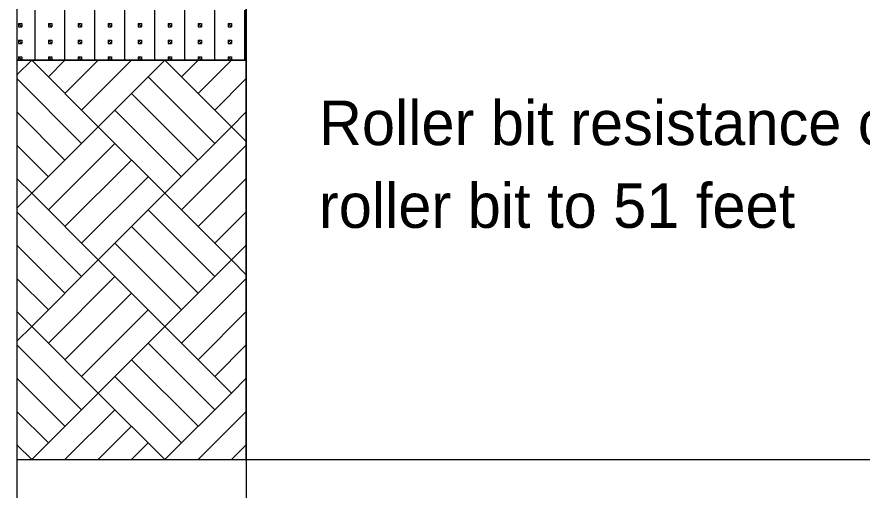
# Model space of a CAD drawing. Extents: x 9422 to 9552, y 6780 to 6860.
# Drawn here: x 9438.314 to 9442.547, y 6795.858 to 6798.227 of the extents above; entities that cross this region are included whole.
import ezdxf

# ---------------------------------------------------------------- set-up
doc = ezdxf.new("R2010")
doc.units = 0
doc.layers.add('7', color=7, linetype='Continuous')
doc.layers.add('8', color=7, linetype='Continuous')

msp = doc.modelspace()

# ---------------------------------------------------------------- linework, layer by layer
at = {"layer": '7'}
for p, q in [((9438.3144, 6822.0107), (9438.3144, 6798.0107)), ((9439.4627, 6798.0107), (9439.4627, 6822.0107)), ((9438.3144, 6798.0107), (9438.3144, 6797.0107)), ((9439.4627, 6798.0107), (9438.3144, 6798.0107)), ((9438.3144, 6798.0107), (9439.4627, 6798.0107)), ((9439.4627, 6797.0107), (9439.4627, 6798.0107)), ((9438.3144, 6797.0107), (9438.3144, 6796.0107)), ((9439.4627, 6796.0107), (9439.4627, 6797.0107)), ((9438.3144, 6796.0107), (9439.4627, 6796.0107))]:
    msp.add_line(p, q, dxfattribs=at)
for points in [[(9438.3144, 6822.0384), (9438.3144, 6796.9829)], [(9439.4627, 6822.0384), (9439.4627, 6796.9829)], [(9438.3144, 6797.0385), (9438.3144, 6792.0107)], [(9439.4627, 6797.0385), (9439.4627, 6792.0107)], [(9439.4627, 6796.0107), (9450.4053, 6796.0107)]]:
    msp.add_lwpolyline(points, dxfattribs=at)
at = {"layer": '8'}
for p, q in [((9438.4053, 6798.1774), (9438.4053, 6798.2607)), ((9438.5553, 6798.1774), (9438.5553, 6798.2607)), ((9438.7053, 6798.1774), (9438.7053, 6798.2607)), ((9438.8553, 6798.1774), (9438.8553, 6798.2607)), ((9439.0053, 6798.1774), (9439.0053, 6798.2607)), ((9439.1553, 6798.1774), (9439.1553, 6798.2607)), ((9439.3053, 6798.1774), (9439.3053, 6798.2607)), ((9439.4553, 6798.1774), (9439.4553, 6798.2607)), ((9438.4053, 6798.094), (9438.4053, 6798.1774)), ((9438.5553, 6798.094), (9438.5553, 6798.1774)), ((9438.7053, 6798.094), (9438.7053, 6798.1774)), ((9438.8553, 6798.094), (9438.8553, 6798.1774)), ((9439.0053, 6798.094), (9439.0053, 6798.1774)), ((9439.1553, 6798.094), (9439.1553, 6798.1774)), ((9439.3053, 6798.094), (9439.3053, 6798.1774)), ((9439.4553, 6798.094), (9439.4553, 6798.1774)), ((9438.4053, 6798.0107), (9438.4053, 6798.094)), ((9438.5553, 6798.0107), (9438.5553, 6798.094)), ((9438.7053, 6798.0107), (9438.7053, 6798.094)), ((9438.8553, 6798.0107), (9438.8553, 6798.094)), ((9439.0053, 6798.0107), (9439.0053, 6798.094)), ((9439.1553, 6798.0107), (9439.1553, 6798.094)), ((9439.3053, 6798.0107), (9439.3053, 6798.094)), ((9439.4553, 6798.0107), (9439.4553, 6798.094)), ((9438.3886, 6798.0107), (9438.3144, 6797.9366)), ((9438.3886, 6798.0107), (9438.7219, 6797.6774)), ((9438.3886, 6798.0107), (9438.3886, 6798.0107)), ((9438.5553, 6798.0107), (9438.4719, 6797.9274)), ((9438.7219, 6798.0107), (9438.5553, 6797.844)), ((9438.8886, 6798.0107), (9438.6386, 6797.7607)), ((9439.0553, 6798.0107), (9438.7219, 6797.6774)), ((9439.0553, 6798.0107), (9438.7219, 6797.6774)), ((9439.0553, 6798.0107), (9439.0553, 6798.0107)), ((9439.0553, 6798.0107), (9439.3886, 6797.6774)), ((9439.0553, 6798.0107), (9439.0553, 6798.0107)), ((9439.2219, 6798.0107), (9439.1386, 6797.9274)), ((9439.3886, 6798.0107), (9439.2219, 6797.844)), ((9438.3144, 6797.9182), (9438.6386, 6797.594)), ((9438.9719, 6797.9274), (9439.3053, 6797.594)), ((9439.4627, 6797.9182), (9439.3053, 6797.7607)), ((9438.8886, 6797.844), (9439.2219, 6797.5107)), ((9438.3144, 6797.7515), (9438.5553, 6797.5107)), ((9438.8053, 6797.7607), (9439.1386, 6797.4274)), ((9439.4627, 6797.7515), (9439.3886, 6797.6774)), ((9439.4627, 6797.7515), (9439.3886, 6797.6774)), ((9438.7219, 6797.6774), (9438.3886, 6797.344)), ((9438.7219, 6797.6774), (9438.3886, 6797.344)), ((9439.0553, 6797.344), (9438.7219, 6797.6774)), ((9438.7219, 6797.6774), (9439.0553, 6797.344)), ((9439.3886, 6797.6774), (9439.0553, 6797.344)), ((9439.3886, 6797.6774), (9439.0553, 6797.344)), ((9439.4627, 6797.6032), (9439.3886, 6797.6774)), ((9439.3886, 6797.6774), (9439.4627, 6797.6032)), ((9438.3144, 6797.5848), (9438.4719, 6797.4274)), ((9438.8053, 6797.594), (9438.4719, 6797.2607)), ((9439.4627, 6797.5848), (9439.1386, 6797.2607)), ((9438.8886, 6797.5107), (9438.5553, 6797.1774)), ((9438.3886, 6797.344), (9438.3144, 6797.4182)), ((9438.9719, 6797.4274), (9438.6386, 6797.094)), ((9439.4627, 6797.4182), (9439.2219, 6797.1774)), ((9438.3886, 6797.344), (9438.3144, 6797.2699)), ((9438.3886, 6797.344), (9438.7219, 6797.0107)), ((9439.0553, 6797.344), (9438.7219, 6797.0107)), ((9439.0553, 6797.344), (9439.3886, 6797.0107)), ((9438.3144, 6797.2515), (9438.6386, 6796.9274)), ((9438.9719, 6797.2607), (9439.3053, 6796.9274)), ((9439.4627, 6797.2515), (9439.3053, 6797.094)), ((9438.8886, 6797.1774), (9439.2219, 6796.844)), ((9438.3144, 6797.0848), (9438.5553, 6796.844)), ((9438.8053, 6797.094), (9439.1386, 6796.7607)), ((9439.4627, 6797.0848), (9439.3886, 6797.0107)), ((9439.4627, 6797.0848), (9439.3886, 6797.0107)), ((9438.7219, 6797.0107), (9438.3886, 6796.6774)), ((9438.7219, 6797.0107), (9438.3886, 6796.6774)), ((9438.7219, 6797.0107), (9438.7219, 6797.0107)), ((9438.7219, 6797.0107), (9438.7219, 6797.0107)), ((9438.7219, 6797.0107), (9438.7219, 6797.0107)), ((9438.7219, 6797.0107), (9438.7219, 6797.0107)), ((9438.7219, 6797.0107), (9439.0553, 6796.6774)), ((9439.3886, 6797.0107), (9439.0553, 6796.6774)), ((9439.3886, 6797.0107), (9439.3886, 6797.0107)), ((9439.3886, 6797.0107), (9439.3886, 6797.0107)), ((9439.3886, 6797.0107), (9439.3886, 6797.0107)), ((9439.3886, 6797.0107), (9439.3886, 6797.0107)), ((9439.3886, 6797.0107), (9439.4627, 6796.9365)), ((9438.3144, 6796.9182), (9438.4719, 6796.7607)), ((9438.8053, 6796.9274), (9438.4719, 6796.594)), ((9439.4627, 6796.9182), (9439.1386, 6796.594)), ((9438.8886, 6796.844), (9438.5553, 6796.5107)), ((9438.3886, 6796.6774), (9438.3145, 6796.7515)), ((9438.9719, 6796.7607), (9438.6386, 6796.4274)), ((9439.4627, 6796.7515), (9439.2219, 6796.5107)), ((9438.3886, 6796.6774), (9438.3145, 6796.6032)), ((9438.3886, 6796.6774), (9438.7219, 6796.344)), ((9439.0553, 6796.6774), (9438.7219, 6796.344)), ((9439.0553, 6796.6774), (9439.3886, 6796.344)), ((9438.9719, 6796.594), (9439.3053, 6796.2607)), ((9438.3144, 6796.5848), (9438.6386, 6796.2607)), ((9439.4627, 6796.5848), (9439.3053, 6796.4274)), ((9438.8886, 6796.5107), (9439.2219, 6796.1774)), ((9438.8053, 6796.4274), (9439.1386, 6796.094)), ((9438.3144, 6796.4182), (9438.5553, 6796.1774)), ((9439.4627, 6796.4182), (9439.3886, 6796.344)), ((9439.4627, 6796.4182), (9439.3886, 6796.344)), ((9438.7219, 6796.344), (9438.3886, 6796.0107)), ((9438.7219, 6796.344), (9438.3886, 6796.0107)), ((9438.7219, 6796.344), (9439.0553, 6796.0107)), ((9439.3886, 6796.344), (9439.0553, 6796.0107)), ((9439.3886, 6796.344), (9439.3886, 6796.344)), ((9439.3886, 6796.344), (9439.3886, 6796.344)), ((9439.3886, 6796.344), (9439.3886, 6796.344)), ((9439.3886, 6796.344), (9439.3886, 6796.344)), ((9438.8053, 6796.2607), (9438.5553, 6796.0107)), ((9438.3144, 6796.2515), (9438.4719, 6796.094)), ((9439.4627, 6796.2515), (9439.2219, 6796.0107)), ((9438.8886, 6796.1774), (9438.7219, 6796.0107)), ((9438.9719, 6796.094), (9438.8886, 6796.0107)), ((9439.4627, 6796.0849), (9439.3886, 6796.0107)), ((9438.3886, 6796.0107), (9438.3145, 6796.0848)), ((9438.7219, 6796.0107), (9438.7219, 6796.0107)), ((9438.7219, 6796.0107), (9438.7219, 6796.0107)), ((9438.7219, 6796.0107), (9438.7219, 6796.0107)), ((9438.7219, 6796.0107), (9438.7219, 6796.0107)), ((9439.3886, 6796.0107), (9439.3886, 6796.0107)), ((9439.3886, 6796.0107), (9439.3886, 6796.0107)), ((9439.3886, 6796.0107), (9439.3886, 6796.0107)), ((9439.3886, 6796.0107), (9439.3886, 6796.0107))]:
    msp.add_line(p, q, dxfattribs=at)
for points in [[(9438.3219, 6798.1774), (9438.3386, 6798.1774), (9438.3219, 6798.194)], [(9438.3386, 6798.194), (9438.3386, 6798.1774), (9438.3219, 6798.194), (9438.3386, 6798.194)], [(9438.4719, 6798.1774), (9438.4886, 6798.1774), (9438.4719, 6798.194)], [(9438.4886, 6798.194), (9438.4886, 6798.1774), (9438.4719, 6798.194), (9438.4886, 6798.194)], [(9438.6219, 6798.1774), (9438.6386, 6798.1774), (9438.6219, 6798.194)], [(9438.6386, 6798.194), (9438.6386, 6798.1774), (9438.6219, 6798.194), (9438.6386, 6798.194)], [(9438.7719, 6798.1774), (9438.7886, 6798.1774), (9438.7719, 6798.194)], [(9438.7886, 6798.194), (9438.7886, 6798.1774), (9438.7719, 6798.194), (9438.7886, 6798.194)], [(9438.9219, 6798.1774), (9438.9386, 6798.1774), (9438.9219, 6798.194)], [(9438.9386, 6798.194), (9438.9386, 6798.1774), (9438.9219, 6798.194), (9438.9386, 6798.194)], [(9439.0719, 6798.1774), (9439.0886, 6798.1774), (9439.0719, 6798.194)], [(9439.0886, 6798.194), (9439.0886, 6798.1774), (9439.0719, 6798.194), (9439.0886, 6798.194)], [(9439.2219, 6798.1774), (9439.2386, 6798.1774), (9439.2219, 6798.194)], [(9439.2386, 6798.194), (9439.2386, 6798.1774), (9439.2219, 6798.194), (9439.2386, 6798.194)], [(9439.3719, 6798.1774), (9439.3886, 6798.1774), (9439.3719, 6798.194)], [(9439.3886, 6798.194), (9439.3886, 6798.1774), (9439.3719, 6798.194), (9439.3886, 6798.194)], [(9438.3219, 6798.094), (9438.3386, 6798.094), (9438.3219, 6798.1107)], [(9438.3386, 6798.1107), (9438.3386, 6798.094), (9438.3219, 6798.1107), (9438.3386, 6798.1107)], [(9438.4719, 6798.094), (9438.4886, 6798.094), (9438.4719, 6798.1107)], [(9438.4886, 6798.1107), (9438.4886, 6798.094), (9438.4719, 6798.1107), (9438.4886, 6798.1107)], [(9438.6219, 6798.094), (9438.6386, 6798.094), (9438.6219, 6798.1107)], [(9438.6386, 6798.1107), (9438.6386, 6798.094), (9438.6219, 6798.1107), (9438.6386, 6798.1107)], [(9438.7719, 6798.094), (9438.7886, 6798.094), (9438.7719, 6798.1107)], [(9438.7886, 6798.1107), (9438.7886, 6798.094), (9438.7719, 6798.1107), (9438.7886, 6798.1107)], [(9438.9219, 6798.094), (9438.9386, 6798.094), (9438.9219, 6798.1107)], [(9438.9386, 6798.1107), (9438.9386, 6798.094), (9438.9219, 6798.1107), (9438.9386, 6798.1107)], [(9439.0719, 6798.094), (9439.0886, 6798.094), (9439.0719, 6798.1107)], [(9439.0886, 6798.1107), (9439.0886, 6798.094), (9439.0719, 6798.1107), (9439.0886, 6798.1107)], [(9439.2219, 6798.094), (9439.2386, 6798.094), (9439.2219, 6798.1107)], [(9439.2386, 6798.1107), (9439.2386, 6798.094), (9439.2219, 6798.1107), (9439.2386, 6798.1107)], [(9439.3719, 6798.094), (9439.3886, 6798.094), (9439.3719, 6798.1107)], [(9439.3886, 6798.1107), (9439.3886, 6798.094), (9439.3719, 6798.1107), (9439.3886, 6798.1107)], [(9438.3219, 6798.0107), (9438.3386, 6798.0107), (9438.3219, 6798.0274)], [(9438.3386, 6798.0274), (9438.3386, 6798.0107), (9438.3219, 6798.0274), (9438.3386, 6798.0274)], [(9438.4719, 6798.0107), (9438.4886, 6798.0107), (9438.4719, 6798.0274)], [(9438.4886, 6798.0274), (9438.4886, 6798.0107), (9438.4719, 6798.0274), (9438.4886, 6798.0274)], [(9438.6219, 6798.0107), (9438.6386, 6798.0107), (9438.6219, 6798.0274)], [(9438.6386, 6798.0274), (9438.6386, 6798.0107), (9438.6219, 6798.0274), (9438.6386, 6798.0274)], [(9438.7719, 6798.0107), (9438.7886, 6798.0107), (9438.7719, 6798.0274)], [(9438.7886, 6798.0274), (9438.7886, 6798.0107), (9438.7719, 6798.0274), (9438.7886, 6798.0274)], [(9438.9219, 6798.0107), (9438.9386, 6798.0107), (9438.9219, 6798.0274)], [(9438.9386, 6798.0274), (9438.9386, 6798.0107), (9438.9219, 6798.0274), (9438.9386, 6798.0274)], [(9439.0719, 6798.0107), (9439.0886, 6798.0107), (9439.0719, 6798.0274)], [(9439.0886, 6798.0274), (9439.0886, 6798.0107), (9439.0719, 6798.0274), (9439.0886, 6798.0274)], [(9439.2219, 6798.0107), (9439.2386, 6798.0107), (9439.2219, 6798.0274)], [(9439.2386, 6798.0274), (9439.2386, 6798.0107), (9439.2219, 6798.0274), (9439.2386, 6798.0274)], [(9439.3719, 6798.0107), (9439.3886, 6798.0107), (9439.3719, 6798.0274)], [(9439.3886, 6798.0274), (9439.3886, 6798.0107), (9439.3719, 6798.0274), (9439.3886, 6798.0274)]]:
    msp.add_lwpolyline(points, close=True, dxfattribs=at)

# ---------------------------------------------------------------- texts
at = {"layer": '7'}
for s, p in [('Roller bit resistance on probable bedrock at 49 feet,', (9439.8273, 6797.5854)), ('roller bit to 51 feet', (9439.8273, 6797.1711))]:
    msp.add_text(s, height=0.2228, dxfattribs=at).set_placement(p)

doc.saveas('drawing.dxf')
